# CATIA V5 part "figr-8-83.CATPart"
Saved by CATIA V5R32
Part number: Part1
Bounding box of the stored display mesh (mm): x -44.701 to 35.128, y -43.586 to 25.876, z -47.191 to 31.322
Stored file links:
  D:\PROJECTS\Project 2022\CATIA V5 6R 2022\Resources\Part Files\c08_catia_v5_6r2022_prt\figr-8-83.CATPart
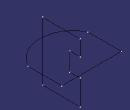
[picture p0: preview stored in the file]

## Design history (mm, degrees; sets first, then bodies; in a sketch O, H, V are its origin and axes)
Body1 (main body)
  Sketch1 on xy-plane, origin (0, 0, 0), H (1, 0, 0), V (0, 1, 0)
    line L1 (-44.7013, 25.8759) -> (35.1284, 25.8759)
    line L2 (35.1284, 25.8759) -> (35.1284, -18.9612)
    line L3 (-44.7013, 25.8759) -> (-44.7013, -18.9612)
    arc A1 centre (-4.7865, 1.0752) radius 44.6615 from (-44.7013, -18.9612) to (35.1284, -18.9612) ccw
    horizontal: L1 H
    vertical: L2 V, L3 V
  Sketch2 on yz-plane, origin (0, 0, 0), H (0, 1, 0), V (0, 0, 1)
    line L1 (-35.2302, 31.3221) -> (-35.2302, -47.1914)
    point P2 (-35.2302, -47.1914)
    point P3 (-35.2302, -47.1914)
    line L2 (-35.2302, -47.1914) -> (15.3919, -47.1914)
    point P4 (15.3919, -47.1914)
    line L3 (15.3919, 31.3221) -> (-35.2302, 31.3221)
    line L4 (15.3919, 31.3221) -> (15.3919, 10.6589)
    line L5 (15.3919, 10.6589) -> (1.7321, 10.6589)
    line L6 (1.7321, 10.6589) -> (1.7321, -13.9018)
    line L7 (1.7321, -13.9018) -> (15.3919, -13.9018)
    point P9 (15.3919, -13.9018)
    line L8 (15.3919, -13.9018) -> (15.3919, -47.1914)
    point P10 (15.3919, -47.1914)
    vertical: L1 V, L4 V, L6 V, L8 V
    horizontal: L2 H, L3 H, L5 H, L7 H
    coincidence: P9 L4, P10 L2, P10 P4, P3 P2
  SolidCombine1: FirstComponentDirection Sketch1, FirstComponentProfile Sketch1, SecondComponentDirection Sketch2, SecondComponentProfile Sketch2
